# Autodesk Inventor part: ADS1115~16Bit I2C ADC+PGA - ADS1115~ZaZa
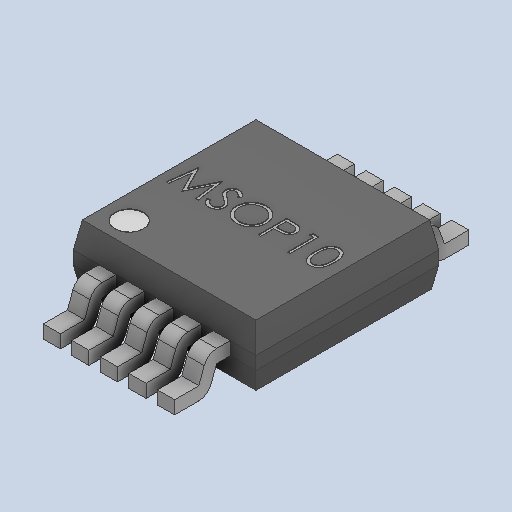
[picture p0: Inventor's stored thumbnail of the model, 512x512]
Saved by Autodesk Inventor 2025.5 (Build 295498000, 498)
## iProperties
Created: 2026-10
Part Number: ADS1115~16Bit I2C ADC+PGA - ADS1115~ZaZa
Material: Genérico
Description: MSOP10
Document SubType Name: Modeling
Designer: Luis M
Density: 1 g/cm^3
Appearance: Valor por defecto
Author: Luis M
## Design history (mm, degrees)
feature "Base1"
node "Sólido1"
